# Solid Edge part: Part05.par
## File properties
Author: Robert a Rhodes jr
Template: Normal.par
Last saved by: Ashutosh-CADCIM
Revision: 5
Application: Solid Edge
Accuracy: 0.99
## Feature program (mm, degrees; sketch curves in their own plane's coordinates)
body "unnamed Body 1"
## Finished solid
Body 1: solid body, 82 faces, 169 edges, 90 vertices.
  Faces by surface: cylinder 44, plane 27, torus 6, spline 3, cone 2
  Edges by curve: circle 64, ellipse 44, line 26, intersection 24, curve on surface 11
Bounding box of the edges (mm; curved faces can reach further): 3403.600 x 1854.200 x 1930.410, from (-1701.8, 0, -965.2014) to (1701.8, 1854.2, 965.2088).
Cylindrical faces by radius (mm): R63.5 x26, R76.2 x4, R95.25 x4, R317.5 x4, R342.9 x3, R558.8 x1, R965.2 x2
Conical faces (half-angle, radius in mm at the cone's reference point): 15 deg R654.5026 x1, 16.46 deg R711.4955 x1
Toroidal faces (ring radius, tube radius in mm): R408.1559 r101.6 x1, R609.6 r50.8 x1, R851.7802 r50.8 x1, R889 r76.2 x2, R983.9044 r127 x1
Planar faces by outward normal: +y 20, +z 1, -y 5, -z 1
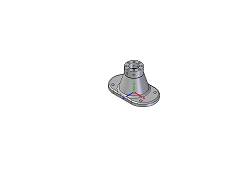
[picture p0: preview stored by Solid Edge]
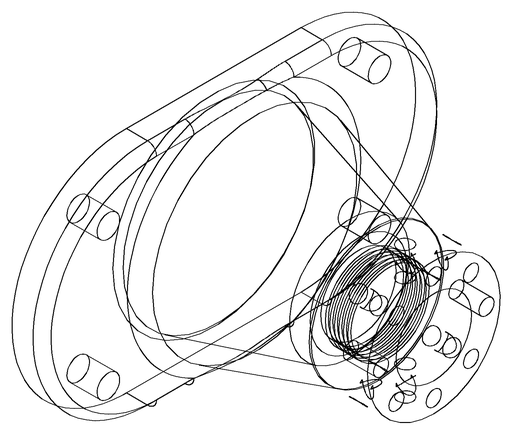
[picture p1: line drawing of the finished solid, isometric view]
